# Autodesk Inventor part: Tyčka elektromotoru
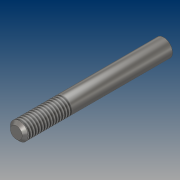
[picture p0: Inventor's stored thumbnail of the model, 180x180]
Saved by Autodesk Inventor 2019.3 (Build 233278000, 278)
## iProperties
Created: 2019-03
Part Number: Tyčka elektromotoru
Material: Ocel, litá
Document SubType Name: Modeling
Designer: B-hon
Density: 7.85 g/cm^3
Appearance: Pololeštěná
Author: B-hon
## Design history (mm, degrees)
sketch "Náčrt1"
  geometry: C1 r 3 at (0, 0); 1 further point
  constraints: 1 centre point, 1 coincident
  dimensions: "d0" = 6 diameter of C1
extrude "Vysunutí1" new body sketch "Náčrt1" distance "d1" = 50; taper "d2" = 0 deg
chamfer "Zkosení1" distance "d3" = 1; stored, may be unused: second distance "d4" = 2, angle "d5" = 45 deg
feature "Závit2" dims "d8" = 15, "d9" = 0
node "Těleso1"
